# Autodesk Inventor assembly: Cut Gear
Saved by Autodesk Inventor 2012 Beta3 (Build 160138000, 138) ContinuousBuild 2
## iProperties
Created: 2011-01
Part Number: Cut Gear
Document SubType Name: Assembly
Designer: Beta-8540w
Categories: <?xml version="1.0" encoding="UTF-16"?> <MemberInstance><Categories><FamilyTemplate/><ParamToTemplateMap><ParamToTemplate><ParamToTemplate CategoryParameter="//
ClientObjectVersion: 1
Author: Beta-8540w
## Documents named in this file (2)
- C:\Inventor 2012 Essentials\Assemblies\Chapter 8\Design Accelerators\Spur Gear c98-01.iam
- C:\Inventor 2012 Essentials\Assemblies\Chapter 8\Design Accelerators\Spur Gear c8-01.ipt
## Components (1 placed, 1 different names)
1. Spur Gear:1
